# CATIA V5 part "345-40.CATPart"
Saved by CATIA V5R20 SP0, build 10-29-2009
Part number: 345-40
Definition: NONE
Nomenclature: 345-40
Source: Unknown
Description: 345-40
Bounding box of the stored display mesh (mm): x 0 to 80, y -41.5 to 41.5, z -41.5 to 41.5
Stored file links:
  C:\Users\Utente\Desktop\IO LAVORO\3D X SITO CF\X SITO\345-346\345-40.CATPart
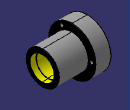
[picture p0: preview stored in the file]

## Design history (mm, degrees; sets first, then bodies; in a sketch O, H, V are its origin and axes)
Body1 "345-40" (main body)
  Solid1: solid without history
